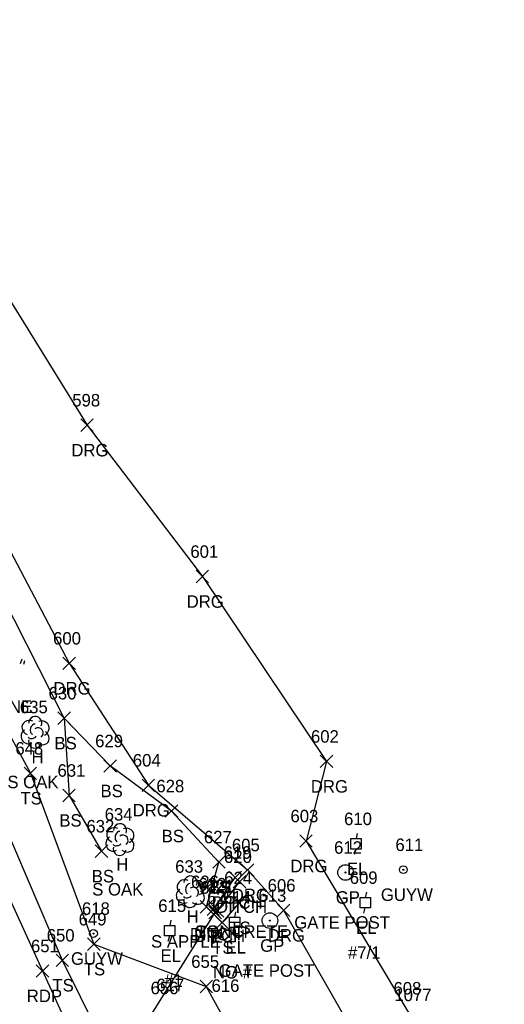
# Model space of a CAD drawing. Extents: x 1647133 to 1649138, y 411736 to 414924.
# Drawn here: x 1648602.7 to 1648680.3, y 412275.3 to 412433 of the extents above; entities that cross this region are included whole.
import ezdxf

# ---------------------------------------------------------------- set-up
doc = ezdxf.new("R2010")
doc.units = 0
for name, color, linetype in [('D_A', 7, 'Continuous'), ('D_C', 7, 'Continuous'), ('D_I', 7, 'Continuous'), ('D_TIC', 7, 'Continuous'), ('DCP', 7, 'Continuous'), ('DD', 7, 'Continuous'), ('L_A', 7, 'Continuous'), ('L_C', 7, 'Continuous'), ('L_I', 7, 'Continuous'), ('L_TIC', 7, 'Continuous'), ('LELB', 7, 'Continuous'), ('LTC', 7, 'Continuous'), ('LTD', 7, 'Continuous'), ('P_A', 7, 'Continuous'), ('P_I', 7, 'Continuous'), ('P_TIC', 7, 'Continuous'), ('PET', 7, 'Continuous'), ('R_A', 7, 'Continuous'), ('R_C', 7, 'Continuous'), ('R_I', 7, 'Continuous'), ('R_TIC', 7, 'Continuous'), ('RDG', 7, 'Continuous'), ('RGP', 7, 'Continuous'), ('S_I', 7, 'Continuous'), ('U_A', 7, 'Continuous'), ('U_C', 7, 'Continuous'), ('U_I', 7, 'Continuous'), ('UEPT', 7, 'Continuous'), ('UPGW', 7, 'Continuous')]:
    doc.layers.add(name, color=color, linetype=linetype)

msp = doc.modelspace()

# ---------------------------------------------------------------- linework, layer by layer
at = {"layer": 'D_TIC'}
for points in [[(1648636.19, 412294.61), (1648638.19, 412296.61)], [(1648638.19, 412294.61), (1648636.19, 412296.61)], [(1648636.89, 412293.94), (1648638.89, 412295.94)], [(1648638.89, 412293.94), (1648636.89, 412295.94)], [(1648632.71, 412289.54), (1648634.71, 412291.54)], [(1648634.71, 412289.54), (1648632.71, 412291.54)], [(1648633, 412289.01), (1648635, 412291.01)], [(1648635, 412289.01), (1648633, 412291.01)], [(1648633.38, 412289.26), (1648635.38, 412291.26)], [(1648635.38, 412289.26), (1648633.38, 412291.26)]]:
    msp.add_lwpolyline(points, dxfattribs=at)
at = {"layer": 'DCP'}
msp.add_lwpolyline([(1648599.37, 412234.61), (1648634, 412290.01)], dxfattribs=at)
at = {"layer": 'DD'}
for points in [[(1648637.19, 412295.61), (1648637.89, 412294.94), (1648634.38, 412290.26), (1648633.71, 412290.54)], [(1648633.71, 412290.54), (1648637.19, 412295.61)]]:
    msp.add_lwpolyline(points, dxfattribs=at)
at = {"layer": 'L_TIC'}
for points in [[(1648608.83, 412320.13), (1648610.83, 412322.13)], [(1648610.83, 412320.13), (1648608.83, 412322.13)], [(1648608.83, 412320.13), (1648610.83, 412322.13)], [(1648610.83, 412320.13), (1648608.83, 412322.13)], [(1648616.19, 412312.47), (1648618.19, 412314.47)], [(1648618.19, 412312.47), (1648616.19, 412314.47)], [(1648603.42, 412311.3), (1648605.42, 412313.3)], [(1648605.42, 412311.3), (1648603.42, 412313.3)], [(1648609.61, 412307.75), (1648611.61, 412309.75)], [(1648611.61, 412307.75), (1648609.61, 412309.75)], [(1648625.99, 412305.25), (1648627.99, 412307.25)], [(1648627.99, 412305.25), (1648625.99, 412307.25)], [(1648614.8, 412298.82), (1648616.8, 412300.82)], [(1648616.8, 412298.82), (1648614.8, 412300.82)], [(1648633.6, 412297.08), (1648635.6, 412299.08)], [(1648635.6, 412297.08), (1648633.6, 412299.08)], [(1648633.6, 412297.08), (1648635.6, 412299.08)], [(1648635.6, 412297.08), (1648633.6, 412299.08)], [(1648631.59, 412289.91), (1648633.59, 412291.91)], [(1648633.59, 412289.91), (1648631.59, 412291.91)], [(1648636.85, 412290.54), (1648638.85, 412292.54)], [(1648638.85, 412290.54), (1648636.85, 412292.54)], [(1648634.11, 412287.38), (1648636.11, 412289.38)], [(1648636.11, 412287.38), (1648634.11, 412289.38)], [(1648613.56, 412283.93), (1648615.56, 412285.93)], [(1648615.56, 412283.93), (1648613.56, 412285.93)], [(1648608.53, 412281.35), (1648610.53, 412283.35)], [(1648610.53, 412281.35), (1648608.53, 412283.35)], [(1648631.57, 412277.14), (1648633.57, 412279.14)], [(1648633.57, 412277.14), (1648631.57, 412279.14)]]:
    msp.add_lwpolyline(points, dxfattribs=at)
at = {"layer": 'LELB'}
for points in [[(1648634.6, 412298.08), (1648626.99, 412306.25), (1648617.19, 412313.47), (1648609.83, 412321.13), (1648597.76, 412344.82), (1648589.36, 412360.72), (1648581.87, 412369.49), (1648576.01, 412375.61)], [(1648569.55, 412372.01), (1648582.32, 412342.11), (1648598.27, 412308.65), (1648609.53, 412282.35), (1648621.03, 412259.1), (1648624.78, 412251.33), (1648635.37, 412226.99), (1648645.42, 412206.79), (1648666.11, 412172.04)], [(1648587.05, 412344.26), (1648604.42, 412312.3), (1648614.56, 412284.93), (1648632.57, 412278.14), (1648641.62, 412261.65)], [(1648609.83, 412321.13), (1648610.61, 412308.75), (1648615.8, 412299.82)], [(1648637.85, 412291.54), (1648635.11, 412288.38), (1648632.59, 412290.91), (1648634.6, 412298.08)]]:
    msp.add_lwpolyline(points, dxfattribs=at)
at = {"layer": 'LTC'}
for p, q in [((1648603.04, 412330.56), (1648602.8, 412329.83)), ((1648603.48, 412330.31), (1648603.3, 412329.74))]:
    msp.add_line(p, q, dxfattribs=at)
at = {"layer": 'LTD'}
for p, q in [((1648605.15, 412318.91), (1648605.15, 412318.91)), ((1648605.15, 412318.91), (1648605.15, 412318.91)), ((1648618.72, 412301.72), (1648618.72, 412301.72)), ((1648618.72, 412301.72), (1648618.72, 412301.72)), ((1648630, 412293.37), (1648630, 412293.37)), ((1648630, 412293.37), (1648630, 412293.37))]:
    msp.add_line(p, q, dxfattribs=at)
for centre in [(1648605.2, 412320.35), (1648618.77, 412303.16), (1648630.05, 412294.81)]:
    msp.add_arc(centre, 1.05, 335.5272, 180.9563, dxfattribs=at)
for centre, major_axis, ratio, start_param, end_param in [((1648604.36, 412319.58), (1.21, -0.51), 0.895232, 1.570796, 4.712389), ((1648604.95, 412319.37), (-0.208, -0.792), 0.645439, 3.141593, 6.283185), ((1648606.2, 412319.5), (-1.14, -0.48), 0.949671, 1.570796, 4.712389), ((1648604.07, 412318.21), (0.58, -1.04), 0.959034, 3.141593, 6.283185), ((1648605.65, 412318.75), (-0.5, 0.667), 0.989748, 3.141593, 6.283185), ((1648606.15, 412318.08), (-1.09, 0.79), 0.841452, 1.570796, 4.712389), ((1648605.15, 412317.41), (0.26, 1.06), 0.942809, 1.570796, 4.712389), ((1648604.7, 412318.16), (-0.625, -0.083), 0.423636, 0, 3.141593), ((1648617.93, 412302.39), (1.21, -0.51), 0.895232, 1.570796, 4.712389), ((1648618.52, 412302.18), (-0.208, -0.792), 0.645439, 3.141593, 6.283185), ((1648619.77, 412302.31), (-1.14, -0.48), 0.949671, 1.570796, 4.712389), ((1648617.64, 412301.01), (0.58, -1.04), 0.959034, 3.141593, 6.283185), ((1648619.22, 412301.56), (-0.5, 0.667), 0.989748, 3.141593, 6.283185), ((1648619.72, 412300.89), (-1.09, 0.79), 0.841452, 1.570796, 4.712389), ((1648618.72, 412300.22), (0.26, 1.06), 0.942809, 1.570796, 4.712389), ((1648618.27, 412300.97), (-0.625, -0.083), 0.423636, 0, 3.141593), ((1648629.21, 412294.04), (1.21, -0.51), 0.895232, 1.570796, 4.712389), ((1648631.04, 412293.96), (-1.14, -0.48), 0.949671, 1.570796, 4.712389), ((1648628.92, 412292.66), (0.58, -1.04), 0.959034, 3.141593, 6.283185), ((1648629.79, 412293.83), (-0.208, -0.792), 0.645439, 3.141593, 6.283185), ((1648630.5, 412293.21), (-0.5, 0.667), 0.989748, 3.141593, 6.283185), ((1648631, 412292.54), (-1.09, 0.79), 0.841452, 1.570796, 4.712389), ((1648630, 412291.87), (0.26, 1.06), 0.942809, 1.570796, 4.712389), ((1648629.54, 412292.62), (-0.625, -0.083), 0.423636, 0, 3.141593)]:
    msp.add_ellipse(centre, major_axis=major_axis, ratio=ratio, start_param=start_param, end_param=end_param, dxfattribs=at)
at = {"layer": 'P_TIC'}
for points in [[(1648605.35, 412279.64), (1648607.35, 412281.64)], [(1648607.35, 412279.64), (1648605.35, 412281.64)]]:
    msp.add_lwpolyline(points, dxfattribs=at)
at = {"layer": 'PET'}
msp.add_lwpolyline([(1648536.12, 412433), (1648543.4, 412417.95), (1648546.49, 412415), (1648562.25, 412380.85), (1648562.34, 412375.74), (1648565.29, 412369.17), (1648579.3, 412340.19), (1648594.41, 412306.78), (1648606.35, 412280.64), (1648620.63, 412249.26), (1648631.78, 412225.06), (1648641.27, 412204.57), (1648646.81, 412192.55), (1648664.82, 412155.81), (1648677.43, 412126.91), (1648681.85, 412118.14), (1648693.97, 412097.36), (1648709.51, 412075.41), (1648723.89, 412057.12), (1648746.98, 412031.15), (1648768.7, 412011.08), (1648794.52, 411987.62), (1648826.41, 411959.79)], dxfattribs=at)
at = {"layer": 'R_TIC'}
for points in [[(1648612.48, 412367.05), (1648614.48, 412369.05)], [(1648614.48, 412367.05), (1648612.48, 412369.05)], [(1648630.94, 412342.81), (1648632.94, 412344.81)], [(1648632.94, 412342.81), (1648630.94, 412344.81)], [(1648609.62, 412328.91), (1648611.62, 412330.91)], [(1648611.62, 412328.91), (1648609.62, 412330.91)], [(1648650.81, 412313.2), (1648652.81, 412315.2)], [(1648652.81, 412313.2), (1648650.81, 412315.2)], [(1648622.3, 412309.38), (1648624.3, 412311.38)], [(1648624.3, 412309.38), (1648622.3, 412311.38)], [(1648647.53, 412300.45), (1648649.53, 412302.45)], [(1648649.53, 412300.45), (1648647.53, 412302.45)], [(1648638.16, 412295.81), (1648640.16, 412297.81)], [(1648640.16, 412295.81), (1648638.16, 412297.81)], [(1648643.94, 412289.35), (1648645.94, 412291.35)], [(1648645.94, 412289.35), (1648643.94, 412291.35)]]:
    msp.add_lwpolyline(points, dxfattribs=at)
at = {"layer": 'RDG'}
for points in [[(1648536.12, 412433), (1648547.13, 412425.13), (1648565.19, 412415.41), (1648582.41, 412411.66), (1648597.83, 412393.34), (1648613.48, 412368.05), (1648631.94, 412343.81), (1648651.81, 412314.2), (1648648.53, 412301.45), (1648665.01, 412273.87)], [(1648565.29, 412369.17), (1648569.55, 412372.01), (1648573.92, 412378.2), (1648579.71, 412376.64), (1648596.71, 412356.35), (1648610.62, 412329.91), (1648623.3, 412310.38), (1648639.16, 412296.81), (1648644.94, 412290.35), (1648657.02, 412269.19)]]:
    msp.add_lwpolyline(points, dxfattribs=at)
at = {"layer": 'RGP'}
for p, q in [((1648654.86, 412296.41), (1648654.86, 412296.41)), ((1648642.76, 412288.71), (1648642.76, 412288.71))]:
    msp.add_line(p, q, dxfattribs=at)
for centre, radius in [((1648654.86, 412296.41), 1.25), ((1648654.86, 412296.41), 0.0833), ((1648642.76, 412288.71), 1.25), ((1648642.76, 412288.71), 0.0833)]:
    msp.add_circle(centre, radius, dxfattribs=at)
at = {"layer": 'UEPT'}
for p, q in [((1648655.71, 412300.17), (1648655.71, 412301.84)), ((1648655.71, 412301.84), (1648657.38, 412301.84)), ((1648656.71, 412302.67), (1648656.55, 412301.84)), ((1648657.38, 412301.84), (1648657.38, 412300.17)), ((1648657.38, 412300.17), (1648655.71, 412300.17)), ((1648656.3, 412299.34), (1648656.55, 412300.17)), ((1648656.55, 412301), (1648656.55, 412301)), ((1648657.19, 412290.75), (1648657.19, 412292.41)), ((1648657.19, 412292.41), (1648658.85, 412292.41)), ((1648658.19, 412293.25), (1648658.02, 412292.41)), ((1648658.85, 412292.41), (1648658.85, 412290.75)), ((1648658.85, 412290.75), (1648657.19, 412290.75)), ((1648657.77, 412289.91), (1648658.02, 412290.75)), ((1648658.02, 412291.58), (1648658.02, 412291.58)), ((1648626.88, 412288.76), (1648626.72, 412287.93)), ((1648636.27, 412287.59), (1648636.27, 412289.26)), ((1648636.27, 412289.26), (1648637.94, 412289.26)), ((1648637.27, 412290.09), (1648637.11, 412289.26)), ((1648637.94, 412289.26), (1648637.94, 412287.59)), ((1648625.88, 412286.26), (1648625.88, 412287.93)), ((1648625.88, 412287.93), (1648627.55, 412287.93)), ((1648626.72, 412287.09), (1648626.72, 412287.09)), ((1648627.55, 412287.93), (1648627.55, 412286.26)), ((1648637.94, 412287.59), (1648636.27, 412287.59)), ((1648636.86, 412286.76), (1648637.11, 412287.59)), ((1648637.11, 412288.43), (1648637.11, 412288.43)), ((1648627.55, 412286.26), (1648625.88, 412286.26)), ((1648626.47, 412285.43), (1648626.72, 412286.26))]:
    msp.add_line(p, q, dxfattribs=at)
at = {"layer": 'UPGW'}
for centre, radius in [((1648664.11, 412296.85), 0.625), ((1648664.11, 412296.85), 0.0833), ((1648614.51, 412286.63), 0.625), ((1648614.51, 412286.63), 0.0833)]:
    msp.add_circle(centre, radius, dxfattribs=at)

# ---------------------------------------------------------------- texts
at = {"layer": 'D_A'}
for s, p in [('DITCH', (1648633.42, 412290.61)), ('DITCH', (1648634.13, 412289.94)), ('DITCH', (1648629.94, 412285.54)), ('DITCH', (1648630.62, 412285.26)), ('P', (1648633.37, 412285.01))]:
    msp.add_text(s, height=2, dxfattribs=at).set_placement(p)
at = {"layer": 'D_C'}
msp.add_text('CONCRETE', height=2, dxfattribs=at).set_placement((1648630.65, 412285.94))
at = {"layer": 'D_I'}
for s, p in [('619', (1648635.34, 412298.61)), ('620', (1648635.4, 412297.94)), ('622', (1648631.3, 412293.54)), ('623', (1648631.59, 412293.01)), ('621', (1648632.54, 412293.26))]:
    msp.add_text(s, height=2, dxfattribs=at).set_placement(p)
at = {"layer": 'L_A'}
for s, p in [('BS', (1648608.27, 412316.13)), ('BS', (1648608.27, 412316.13)), ('H', (1648604.59, 412313.91)), ('TS', (1648602.83, 412307.3)), ('BS', (1648615.64, 412308.47)), ('BS', (1648609.05, 412303.75)), ('BS', (1648625.43, 412301.25)), ('H', (1648618.16, 412296.72)), ('BS', (1648614.24, 412294.82)), ('TS', (1648633.01, 412293.08)), ('BS', (1648633.04, 412293.08)), ('H', (1648629.43, 412288.37)), ('TS', (1648631, 412285.91)), ('TS', (1648636.26, 412286.54)), ('TS', (1648633.52, 412283.38)), ('TS', (1648612.97, 412279.93)), ('TS', (1648607.94, 412277.35))]:
    msp.add_text(s, height=2, dxfattribs=at).set_placement(p)
at = {"layer": 'L_C'}
for s, p in [('S PINE', (1648595.93, 412321.97)), ('S OAK', (1648600.74, 412309.91)), ('S OAK', (1648614.31, 412292.72)), ('S APPLE', (1648623.73, 412284.37))]:
    msp.add_text(s, height=2, dxfattribs=at).set_placement(p)
at = {"layer": 'L_I'}
for s, p in [('630', (1648607.33, 412324.13)), ('630', (1648607.33, 412324.13)), ('635', (1648602.74, 412321.91)), ('648', (1648602.01, 412315.3)), ('629', (1648614.78, 412316.47)), ('631', (1648608.76, 412311.75)), ('628', (1648624.58, 412309.25)), ('634', (1648616.31, 412304.72)), ('632', (1648613.39, 412302.82)), ('627', (1648632.19, 412301.08)), ('627', (1648632.19, 412301.08)), ('633', (1648627.59, 412296.37)), ('624', (1648635.44, 412294.54)), ('626', (1648630.12, 412293.91)), ('625', (1648632.7, 412291.38)), ('649', (1648612.14, 412287.93)), ('650', (1648607.03, 412285.35)), ('655', (1648630.16, 412281.14))]:
    msp.add_text(s, height=2, dxfattribs=at).set_placement(p)
at = {"layer": 'P_A'}
msp.add_text('RDP', height=2, dxfattribs=at).set_placement((1648603.84, 412275.64))
at = {"layer": 'P_I'}
msp.add_text('651', height=2, dxfattribs=at).set_placement((1648604.51, 412283.64))
at = {"layer": 'R_A'}
for s, p in [('DRG', (1648610.97, 412363.05)), ('DRG', (1648629.43, 412338.81)), ('DRG', (1648608.11, 412324.91)), ('DRG', (1648649.3, 412309.2)), ('DRG', (1648620.79, 412305.38)), ('DRG', (1648646.02, 412296.45)), ('DRG', (1648636.65, 412291.81)), ('GP', (1648653.29, 412291.41)), ('DRG', (1648642.42, 412285.35)), ('GP', (1648641.19, 412283.71))]:
    msp.add_text(s, height=2, dxfattribs=at).set_placement(p)
at = {"layer": 'R_C'}
for p in [(1648646.65, 412287.41), (1648634.55, 412279.71)]:
    msp.add_text('GATE POST', height=2, dxfattribs=at).set_placement(p)
at = {"layer": 'R_I'}
for s, p in [('598', (1648611.12, 412371.05)), ('601', (1648630.02, 412346.81)), ('600', (1648608.05, 412332.91)), ('602', (1648649.32, 412317.2)), ('604', (1648620.81, 412313.38)), ('603', (1648646.04, 412304.45)), ('605', (1648636.67, 412299.81)), ('612', (1648653.02, 412299.41)), ('606', (1648642.39, 412293.35)), ('613', (1648640.92, 412291.71)), ('608', (1648662.53, 412276.87)), ('1077', (1648662.67, 412275.8))]:
    msp.add_text(s, height=2, dxfattribs=at).set_placement(p)
at = {"layer": 'S_I'}
msp.add_text('656', height=2, dxfattribs=at).set_placement((1648623.65, 412276.91))
at = {"layer": 'U_A'}
for s, p in [('EL', (1648655.08, 412296)), ('GUYW', (1648660.51, 412291.85)), ('EL', (1648656.55, 412286.58)), ('EL', (1648625.25, 412282.09)), ('EL', (1648635.64, 412283.43)), ('GUYW', (1648610.91, 412281.63))]:
    msp.add_text(s, height=2, dxfattribs=at).set_placement(p)
at = {"layer": 'U_C'}
for s, p in [('#7/1', (1648655.25, 412282.58)), ('NO #', (1648633.64, 412279.43)), ('#1', (1648625.82, 412278.09))]:
    msp.add_text(s, height=2, dxfattribs=at).set_placement(p)
at = {"layer": 'U_I'}
for s, p in [('610', (1648654.62, 412304)), ('611', (1648662.84, 412299.85)), ('609', (1648655.52, 412294.58)), ('614', (1648635.26, 412291.43)), ('615', (1648624.88, 412290.09)), ('618', (1648612.67, 412289.63)), ('617', (1648624.58, 412277.4)), ('616', (1648633.41, 412277.29))]:
    msp.add_text(s, height=2, dxfattribs=at).set_placement(p)

doc.saveas('drawing.dxf')
